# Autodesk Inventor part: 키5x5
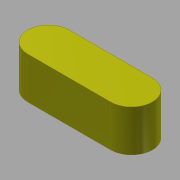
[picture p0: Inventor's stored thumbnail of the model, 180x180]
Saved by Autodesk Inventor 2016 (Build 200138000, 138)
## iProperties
Created: 2011-04
Part Number: 키5x5
Document SubType Name: Modeling
Designer: pww
Density: 7.86 g/cm^3
Material: 강철, 연강
Appearance: 노란색
Author: pww
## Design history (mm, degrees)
sketch "스케치1"
  geometry: L1 (-5, -2.5)-(5, -2.5); L2 (5, 2.5)-(-5, 2.5); A1 r 2.5 centre (-5, 0) between (-5, 2.5) and (-5, -2.5); A2 r 2.5 centre (5, 0) between (5, -2.5) and (5, 2.5); 1 further point
  constraints: 4 end point, 4 point on circle, 2 centre point
extrude "돌출1" new body sketch "스케치1" distance "d0" = 5; taper "d1" = 0 deg
node "솔리드1"
